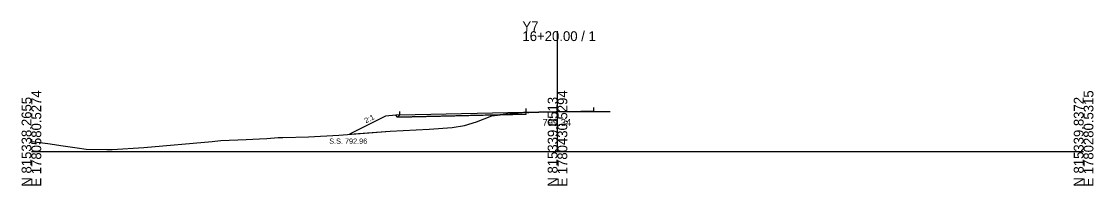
# Model space of a CAD drawing. Extents: x -26 to 2903, y -10 to 5536.
# Drawn here: x 1297.2 to 1602.8, y 490.3 to 537.2 of the extents above; entities that cross this region are included whole.
import ezdxf

# ---------------------------------------------------------------- set-up
doc = ezdxf.new("R2010")
doc.units = 0
for name, color, linetype in [('Exist Cross Section Cell', 7, 'Continuous'), ('Exist XS Center Line Elevation Label', 7, 'Continuous'), ('Exist XS Ground Line', 7, 'Continuous'), ('Prop XS Ditch Slope Text', 7, 'Continuous'), ('Prop XS Dump Level', 7, 'Continuous'), ('Prop XS Earthwork Shape', 7, 'Continuous'), ('Prop XS EOT Tick Mark', 7, 'Continuous'), ('Prop XS Finish Grade', 7, 'Continuous'), ('Prop XS Finish Grade Earthwork', 7, 'Continuous'), ('Prop XS Finish Grade Pavement', 7, 'Continuous'), ('Prop XS Pvmt Edge Slope', 7, 'Continuous'), ('Prop XS SS Elevation Text', 7, 'Continuous'), ('Prop XS Subgrade Earthwork', 7, 'Continuous')]:
    doc.layers.add(name, color=color, linetype=linetype)

msp = doc.modelspace()

# ---------------------------------------------------------------- linework, layer by layer
at = {"layer": 'Exist Cross Section Cell'}
for p, q in [((1450, 500), (1450, 534.35)), ((1300, 500), (1450, 500)), ((1450, 500), (1600, 500))]:
    msp.add_line(p, q, dxfattribs=at)
at = {"layer": 'Exist XS Ground Line'}
for p, q in [((1431.32, 510.24), (1434.49, 510.62)), ((1434.49, 510.62), (1435.27, 510.69)), ((1435.27, 510.69), (1441.07, 511.14)), ((1441.07, 511.14), (1444.68, 511.22)), ((1444.68, 511.22), (1449.67, 511.33)), ((1449.67, 511.33), (1450, 511.34)), ((1450, 511.34), (1456.68, 511.42)), ((1456.68, 511.42), (1460.34, 511.45)), ((1460.34, 511.45), (1465.02, 511.45)), ((1419.94, 506.89), (1423.46, 507.48)), ((1423.46, 507.48), (1426.89, 508.53)), ((1426.89, 508.53), (1431.32, 510.24)), ((1378.99, 504.21), (1387.63, 504.72)), ((1387.63, 504.72), (1402.28, 505.87)), ((1402.28, 505.87), (1413.4, 506.41)), ((1413.4, 506.41), (1419.94, 506.89)), ((1300, 502.93), (1300.84, 502.81)), ((1300.84, 502.81), (1304.67, 502.29)), ((1304.67, 502.29), (1309.05, 501.67)), ((1309.05, 501.67), (1313, 501.08)), ((1332.01, 501.17), (1351.54, 502.9)), ((1351.54, 502.9), (1352.31, 502.95)), ((1352.31, 502.95), (1353.98, 503.14)), ((1353.98, 503.14), (1361.19, 503.41)), ((1361.19, 503.41), (1365.07, 503.6)), ((1365.07, 503.6), (1367.09, 503.75)), ((1367.09, 503.75), (1370.38, 504.01)), ((1370.38, 504.01), (1371.65, 504.03)), ((1371.65, 504.03), (1378.99, 504.21)), ((1313, 501.08), (1315.64, 500.72)), ((1315.64, 500.72), (1321.52, 500.56)), ((1321.52, 500.56), (1323.02, 500.56)), ((1323.02, 500.56), (1332.01, 501.17))]:
    msp.add_line(p, q, dxfattribs=at)
at = {"layer": 'Prop XS Earthwork Shape'}
for points in [[(1403.89, 510.37), (1401, 510.14), (1390.65, 504.96), (1402.28, 505.87), (1413.4, 506.41), (1419.94, 506.89), (1423.46, 507.48), (1426.89, 508.53), (1431.32, 510.24), (1433.59, 510.51), (1404.4, 509.86)], [(1433.59, 510.51), (1441.06, 510.68), (1441.06, 511.14), (1435.27, 510.69), (1434.49, 510.62)]]:
    msp.add_lwpolyline(points, close=True, dxfattribs=at)
at = {"layer": 'Prop XS EOT Tick Mark'}
for p, q in [((1405, 510.46), (1405, 511.46)), ((1441.06, 511.26), (1441.06, 512.26)), ((1460.34, 511.58), (1460.34, 512.58))]:
    msp.add_line(p, q, dxfattribs=at)
at = {"layer": 'Prop XS Finish Grade'}
msp.add_line((1405, 510.46), (1403.89, 510.37), dxfattribs=at)
at = {"layer": 'Prop XS Finish Grade Earthwork'}
for p, q in [((1401, 510.14), (1390.65, 504.96)), ((1403.89, 510.37), (1401, 510.14))]:
    msp.add_line(p, q, dxfattribs=at)
at = {"layer": 'Prop XS Finish Grade Pavement'}
for p, q in [((1405, 510.46), (1444.68, 511.34)), ((1444.68, 511.34), (1449.66, 511.46)), ((1449.67, 511.46), (1450, 511.46)), ((1450, 511.46), (1456.68, 511.54)), ((1456.68, 511.54), (1460.34, 511.58))]:
    msp.add_line(p, q, dxfattribs=at)
at = {"layer": 'Prop XS Pvmt Edge Slope'}
msp.add_line((1405, 510.46), (1404.4, 509.86), dxfattribs=at)
at = {"layer": 'Prop XS Subgrade Earthwork'}
for p, q in [((1404.4, 509.86), (1441.06, 510.68)), ((1441.06, 510.68), (1441.06, 511.14)), ((1404.4, 509.86), (1403.89, 510.37))]:
    msp.add_line(p, q, dxfattribs=at)

# ---------------------------------------------------------------- texts
at = {"layer": 'Exist Cross Section Cell'}
for s, p in [('Y7', (1440, 534.35)), ('16+20.00 / 1', (1440, 531.55))]:
    msp.add_text(s, height=2.8, dxfattribs=at).set_placement(p)
for s, p in [('E 1780580.5274', (1302.8, 490)), ('E 1780430.5294', (1452.8, 490)), ('E 1780280.5315', (1602.8, 490)), ('N 815338.2655', (1300, 490)), ('N 815339.0513', (1450, 490)), ('N 815339.8372', (1600, 490))]:
    msp.add_text(s, height=2.8, rotation=90, dxfattribs=at).set_placement(p)
at = {"layer": 'Exist XS Center Line Elevation Label'}
msp.add_text('799.34', height=2, dxfattribs=at).set_placement((1445.72, 507.34))
at = {"layer": 'Prop XS Ditch Slope Text'}
msp.add_text('2:1', height=1.5, rotation=27.0863, dxfattribs=at).set_placement((1395.4, 508.05))
at = {"layer": 'Prop XS Dump Level'}
msp.add_text('Eop', height=0.3, dxfattribs=at).set_placement((1441.08, 510.84))
msp.add_text('Eop', height=0.3, dxfattribs=at).set_placement((1441.08, 510.84))
at = {"layer": 'Prop XS SS Elevation Text'}
msp.add_text('S.S. 792.96', height=1.5, dxfattribs=at).set_placement((1384.92, 502.23))

doc.saveas('drawing.dxf')
